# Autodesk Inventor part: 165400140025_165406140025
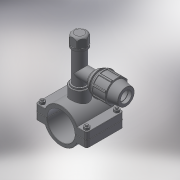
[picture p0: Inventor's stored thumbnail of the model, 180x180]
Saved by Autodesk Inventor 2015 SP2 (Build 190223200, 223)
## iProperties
Created: 2017-05
Part Number: 165400140025_165406140025
Material: Generic
Description: PLASSON TAPPER FOR PE+PVC PIPE 140-25
Document SubType Name: Modeling
Designer: KIM
Density: 1 g/cm^3
Appearance: Default
Author: KIM
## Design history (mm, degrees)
derived "16540.ipt"
feature "Solid1::16540.ipt"
feature "Solid2::16540.ipt"
tag "TaggingFeature1"
body "Solid1"
other parameters: "d0" = 154, "d1" = 201, "d4" = 136, "d5" = 0, "d6" = 10.05, "d7" = 201, "d8" = 0.1, "d10" = 0, "d11" = 1.4, "d14" = 39.3783, "d20" = 1.4, "d23" = 1.4, "d36" = 15, "d37" = 12, "d38" = 78, "d39" = 0, "d40" = 3, "d41" = 5, "d42" = 0, "d44" = 3, "d45" = 0, "d46" = 1.4, "d51" = 101, "d52" = 30.291, "d53" = 21, "d54" = 0, "d55" = 25, "d57" = 0, "d58" = 151.2, "d60" = 0, "d62" = 15, "d63" = 12, "d66" = 112, "d67" = 25, "d68" = 8.75, "d69" = 21, "d70" = 54, "d71" = 40.5, "d72" = 1.5, "d73" = 43.2, "d74" = 120 deg, "d75" = 37.5, "d76" = 10 deg, "d77" = 48.6, "d78" = 31.5, "d79" = 61, "d81" = 105, "d82" = 6.1, "d87" = 15, "d90" = 50.22, "d91" = 35 deg, "d92" = 17.5 deg, "d94" = 0, "d96" = 360 deg, "d98" = 0.5, "d99" = 67.1, "d100" = 27.2619, "d101" = 135 deg, "d102" = 1.08, "d105" = 2.7, "d106" = 0, "d107" = 0.1, "d108" = 27.2619, "d109" = 33.3201, "d111" = 26.4, "d112" = 6.6, "d113" = 3.5, "d116" = 0, "d118" = 21, "d119" = 0, "d121" = 132, "d122" = 59, "B_" = 25, "G_" = 30.291, "A_" = 101, "L_" = 201, "L_1" = 136, "l_2" = 21, "d_1" = 25, "E_" = 54, "l_" = 61, "H_" = 105, "H_1" = 59, "H_2" = 132
